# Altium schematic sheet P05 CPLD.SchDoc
size 297 x 209 mm
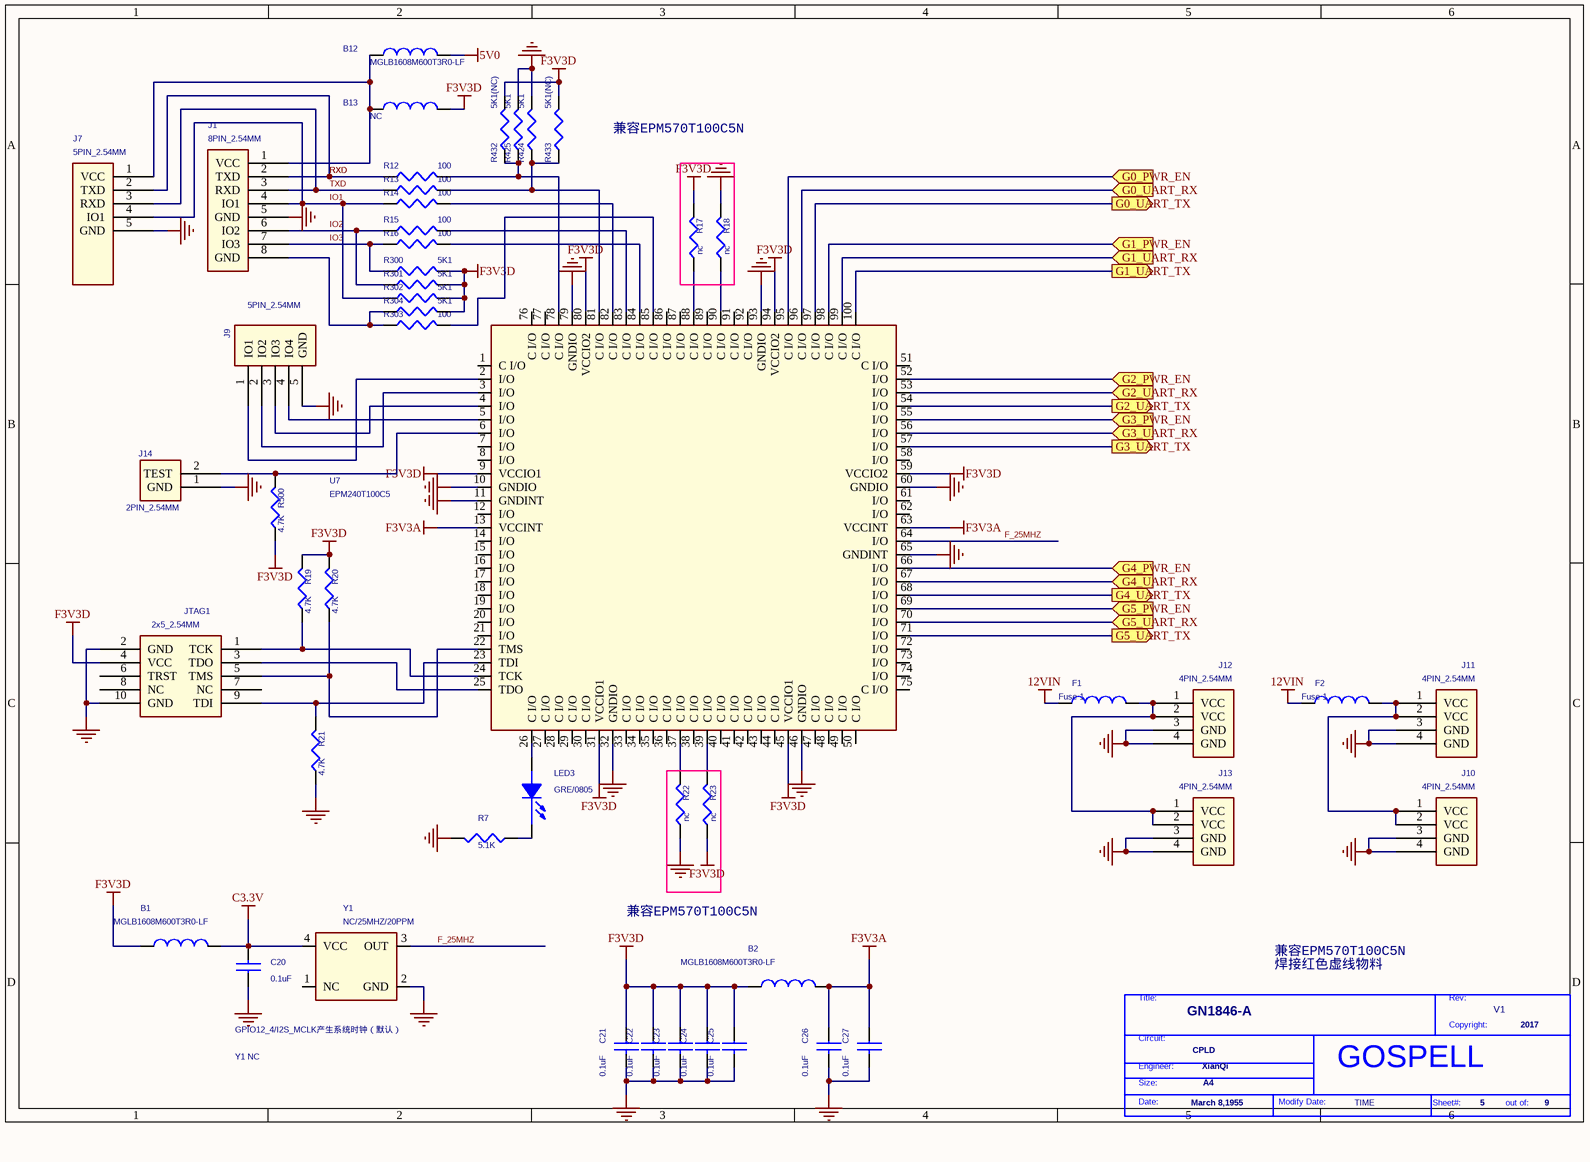
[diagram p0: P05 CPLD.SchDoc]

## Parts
*  Doc: CPLD  Page Count: 9  Page Number: 5  Page Create Date: March 8,1955  Page Size: A4  RevCode: V1  Title: GN1846-A  Copyright: 2017  Engineer: XianQi  Page Modify Date: TIME  (hidden comment: GOSPELL)  (graphical)
B1  MGLB1608M600T3R0-LF  [L0603]
B2  MGLB1608M600T3R0-LF  [L0603]
B12  MGLB1608M600T3R0-LF  [L0603]
B13  NC  [L0603]
C20  0.1uF  [0402C]
C21  0.1uF  [0402C]
C22  0.1uF  [0402C]
C23  0.1uF  [0402C]
C24  0.1uF  [0402C]
C25  0.1uF  [0402C]
C26  0.1uF  [0402C]
C27  0.1uF  [0402C]
F1  Fuse 1  [F15]
F2  Fuse 1  [F15]
J1  8PIN_2.54MM  [CON8_2D54MM_G]
J7  5PIN_2.54MM  [CON5_2D54MM_G]
J9  5PIN_2.54MM  [CON5_2D54MM_G]
J10  4PIN_2.54MM  [SIP4]
J11  4PIN_2.54MM  [SIP4]
J12  4PIN_2.54MM  [SIP4]
J13  4PIN_2.54MM  [SIP4]
J14  2PIN_2.54MM  [CN2]
JTAG1  2x5_2.54MM  [HERDER5X2]
LED3  GRE/0805  [LED0805]
R7  5.1K  [0402R]
R12  100  [0402R]
R13  100  [0402R]
R14  100  [0402R]
R15  100  [0402R]
R16  100  [0402R]
R17  nc  [0402R]
R18  nc  [0402R]
R19  4.7K  [0402R]
R20  4.7K  [0402R]
R21  4.7K  [0402R]
R22  nc  [0402R]
R23  nc  [0402R]
R300  5K1  [0402R]
R301  5K1  [0402R]
R302  5K1  [0402R]
R303  100  [0402R]
R304  5K1  [0402R]
R424  5K1  [0402R]
R425  5K1  [0402R]
R432  5K1(NC)  [0402R]
R433  5K1(NC)  [0402R]
R500  4.7K  [0402R]
U7  EPM240T100C5  [TQFP-100P]
Y1  NC/25MHZ/20PPM  [SCXO_7.0X5.0]

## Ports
G0_PWR_EN (in), G0_UART_RX (in), G0_UART_TX (out), G1_PWR_EN (in), G1_UART_RX (in), G1_UART_TX (out), G2_PWR_EN (in), G2_UART_RX (in), G2_UART_TX (out), G3_PWR_EN (in), G3_UART_RX (in), G3_UART_TX (out), G4_PWR_EN (in), G4_UART_RX (in), G4_UART_TX (out), G5_PWR_EN (in), G5_UART_RX (in), G5_UART_TX (out)

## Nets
5V0: B12.2
12VIN: F1.1 F2.1
C3.3V: B1.2 C20.2 Y1.4(VCC)
F3V3A: B2.2 C26.1 C27.1 U7.13(VCCINT) U7.63(VCCINT)
F3V3D: B1.1 B2.1 B13.2 C21.1 C22.1 C23.1 C24.1 C25.1 JTAG1.4(VCC) R17.1 R19.1 R20.1 R23.2 R300.1 R301.1 R302.1 R304.1 R432.1 R433.1 R500.2 U7.9(VCCIO1) U7.31(VCCIO1) U7.45(VCCIO1) U7.59(VCCIO2) U7.80(VCCIO2) U7.94(VCCIO2)
GND: C20.1 C21.2 C22.2 C23.2 C24.2 C25.2 C26.2 C27.2 J1.5(GND) J7.5(GND) J9.5(GND) J10.3(GND) J10.4(GND) J11.3(GND) J11.4(GND) J12.3(GND) J12.4(GND) J13.3(GND) J13.4(GND) J14.1(GND) JTAG1.2(GND) JTAG1.10(GND) R7.1 R18.1 R21.2 R22.2 R424.1 R425.1 U7.10(GNDIO) U7.11(GNDINT) U7.32(GNDIO) U7.46(GNDIO) U7.60(GNDIO) U7.65(GNDINT) U7.79(GNDIO) U7.93(GNDIO) Y1.2(GND)
F_25MHZ: U7.64(I/O) Y1.3(OUT)
G0_PWR_EN: U7.95(C_I/O) ; port G0_PWR_EN
G0_UART_RX: U7.96(C_I/O) ; port G0_UART_RX
G0_UART_TX: U7.97(C_I/O) ; port G0_UART_TX
G1_PWR_EN: U7.98(C_I/O) ; port G1_PWR_EN
G1_UART_RX: U7.99(C_I/O) ; port G1_UART_RX
G1_UART_TX: U7.100(C_I/O) ; port G1_UART_TX
G2_PWR_EN: U7.52(I/O) ; port G2_PWR_EN
G2_UART_RX: U7.53(I/O) ; port G2_UART_RX
G2_UART_TX: U7.54(I/O) ; port G2_UART_TX
G3_PWR_EN: U7.55(I/O) ; port G3_PWR_EN
G3_UART_RX: U7.56(I/O) ; port G3_UART_RX
G3_UART_TX: U7.57(I/O) ; port G3_UART_TX
G4_PWR_EN: U7.66(I/O) ; port G4_PWR_EN
G4_UART_RX: U7.67(I/O) ; port G4_UART_RX
G4_UART_TX: U7.68(I/O) ; port G4_UART_TX
G5_PWR_EN: U7.69(I/O) ; port G5_PWR_EN
G5_UART_RX: U7.70(I/O) ; port G5_UART_RX
G5_UART_TX: U7.71(I/O) ; port G5_UART_TX
IO1: J1.4(IO1) J7.4(IO1) R14.2 R302.2
IO2: J1.6(IO2) R15.2 R301.2
IO3: J1.7(IO3) R16.2 R300.2
RXD: J1.2(TXD) J7.2(TXD) R12.2
TXD: J1.3(RXD) J7.3(RXD) R13.2
NetB12_1: B12.1 B13.1 J1.1(VCC) J7.1(VCC)
NetF1_2: F1.2 J12.1(VCC) J12.2(VCC) J13.1(VCC) J13.2(VCC)
NetF2_2: F2.2 J10.1(VCC) J10.2(VCC) J11.1(VCC) J11.2(VCC)
NetJ1_8: J1.8(GND) R303.2 R304.2
NetJ9_1: J9.1(IO1) U7.2(I/O)
NetJ9_2: J9.2(IO2) U7.3(I/O)
NetJ9_3: J9.3(IO3) U7.4(I/O)
NetJ9_4: J9.4(IO4) U7.5(I/O)
NetJ14_2: J14.2(TEST) R500.1 U7.6(I/O)
NetJTAG1_1: JTAG1.1(TCK) R19.2 U7.24(TCK)
NetJTAG1_3: JTAG1.3(TDO) U7.25(TDO)
NetJTAG1_5: JTAG1.5(TMS) R20.2 U7.22(TMS)
NetJTAG1_9: JTAG1.9(TDI) R21.1 U7.23(TDI)
NetLED3_A: LED3.A(ANODE) U7.26(C_I/O)
NetLED3_K: LED3.K(CATHODE) R7.2
NetR12_1: R12.1 R425.2 R432.2 U7.78(C_I/O)
NetR13_1: R13.1 R424.2 R433.2 U7.81(C_I/O)
NetR14_1: R14.1 U7.82(C_I/O)
NetR15_1: R15.1 U7.83(C_I/O)
NetR16_1: R16.1 U7.84(C_I/O)
NetR17_2: R17.2 U7.88(C_I/O)
NetR18_2: R18.2 U7.90(C_I/O)
NetR22_1: R22.1 U7.37(C_I/O)
NetR23_1: R23.1 U7.39(C_I/O)
NetR303_1: R303.1 U7.85(C_I/O)

Not connected (* = marked no-connect by the designer): JTAG1 6(TRST) 7(NC) 8(NC); U7 1(C_I/O) 7(I/O) 8(I/O) 12(I/O) 14(I/O) 15(I/O) 16(I/O) 17(I/O) 18(I/O) 19(I/O) 20(I/O) 21(I/O) 27(C_I/O) 28(C_I/O) 29(C_I/O) 30(C_I/O) 33(C_I/O) 34(C_I/O) 35(C_I/O) 36(C_I/O) 38(C_I/O) 40(C_I/O) 41(C_I/O) 42(C_I/O) 43(C_I/O) 44(C_I/O) 47(C_I/O) 48(C_I/O) 49(C_I/O) 50(C_I/O) 51(C_I/O) 58(I/O) 61(I/O) 62(I/O) 72(I/O) 73(I/O) 74(I/O) 75(C_I/O) 76(C_I/O) 77(C_I/O) 86(C_I/O) 87(C_I/O) 89(C_I/O) 91(C_I/O) 92(C_I/O); Y1 1(NC)

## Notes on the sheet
- 兼容EPM570T100C5N
- 焊接红色虚线物料
- GPIO12_4/I2S_MCLK产生系统时钟（默认）
- Y1 NC

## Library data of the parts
B1 B2 B12 B13 F1 F2 = CHOKE TORROID_0
C20 = CAP NP
C21-C27 = CAP NP_Dup1
J1 = CON8_0
J7 J9-J14 = CON8_1
JTAG1 = CON10A_0
LED3 = LED_0
R7 R12-R23 R300-R304 R424 R425 R432 R433 R500 = R_Dup1
Y1 = SCXO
